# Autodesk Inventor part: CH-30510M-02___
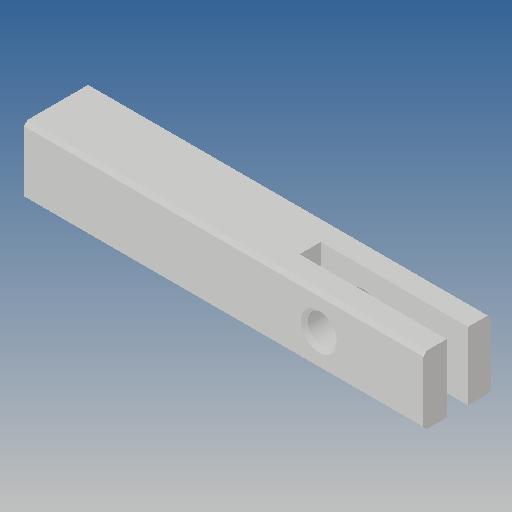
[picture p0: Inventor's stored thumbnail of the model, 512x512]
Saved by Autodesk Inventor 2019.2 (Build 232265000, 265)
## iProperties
Created: 2010-06
Part Number: CH-30510M-02___
Material: Ogólny
Document SubType Name: Modeling
Designer: CADENGINEERING4
Density: 1 g/cm^3
Appearance: Domyślna
Author: CADENGINEERING4
Revision Number: ANY
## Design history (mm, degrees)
feature "NONE"
node "Bryła1"
